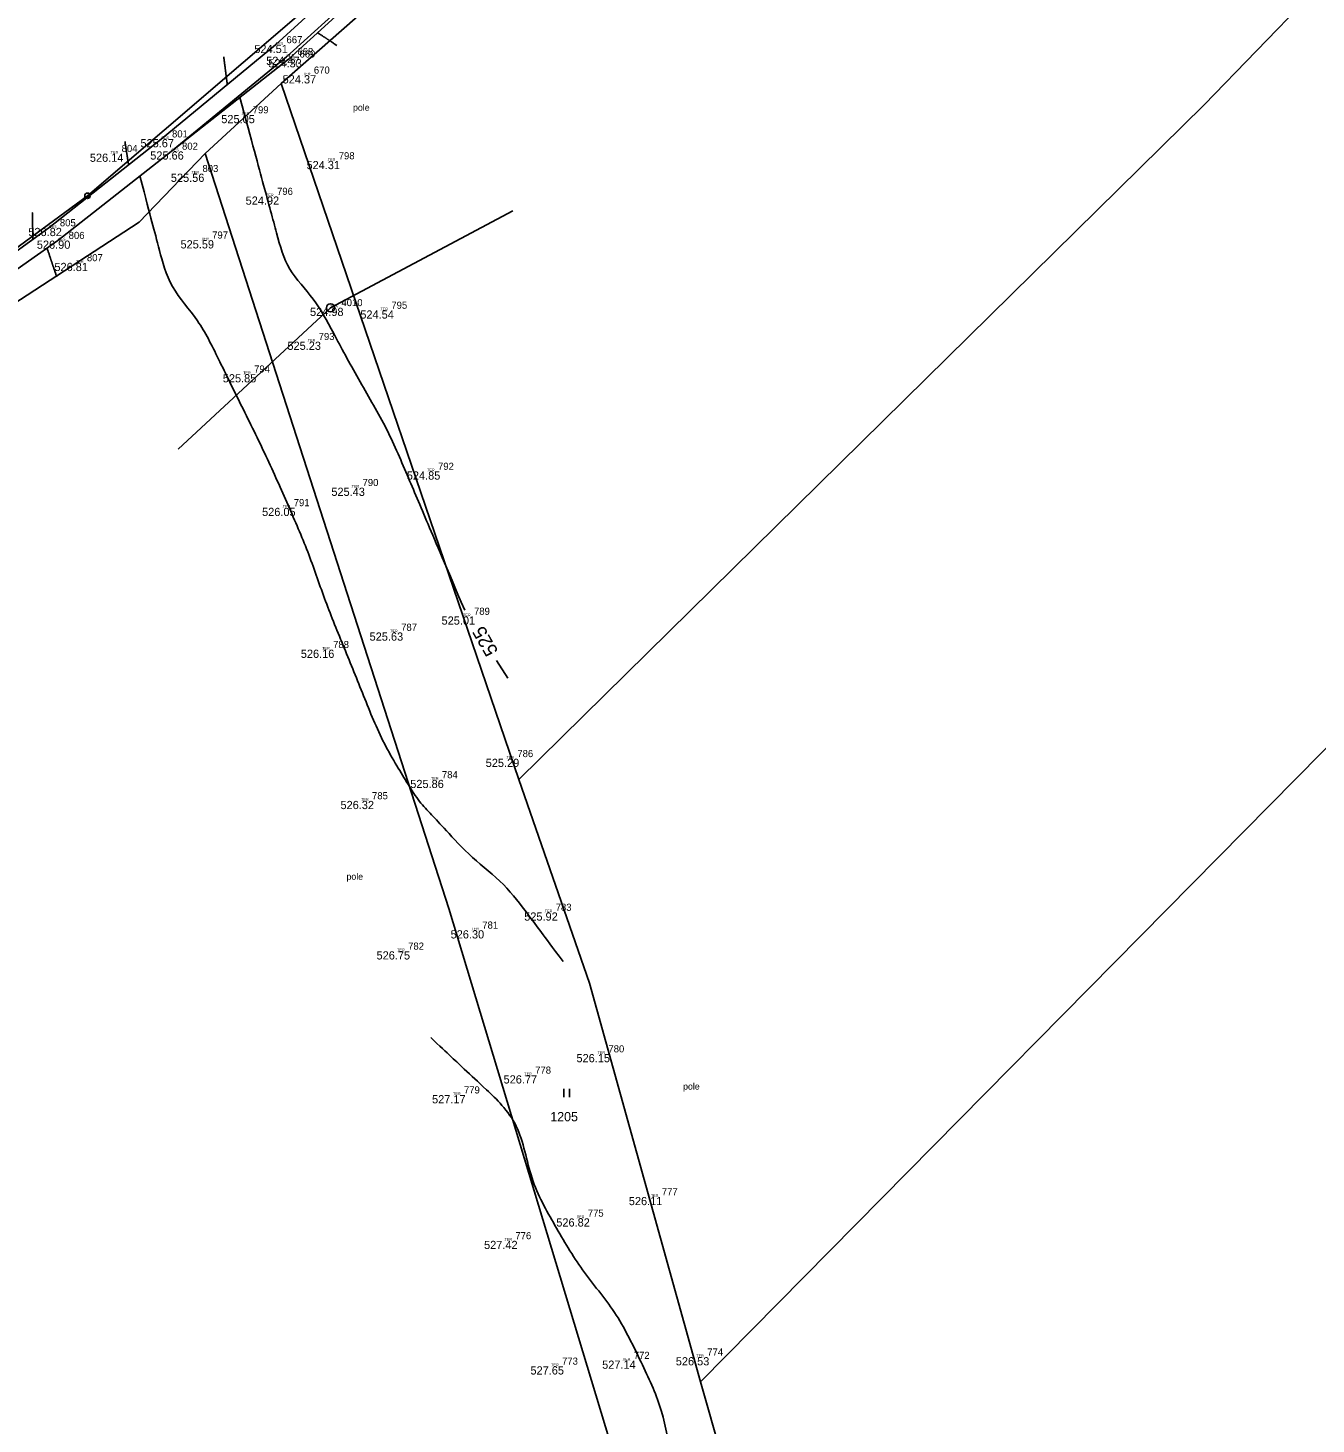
# Model space of a CAD drawing. Extents: x -604848 to -603227, y -1111879 to -1109838.
# Drawn here: x -604243.7 to -604007.9, y -1111222.3 to -1110966.8 of the extents above; entities that cross this region are included whole.
import ezdxf

# ---------------------------------------------------------------- set-up
doc = ezdxf.new("R2010")
doc.units = 0
for name, color, linetype in [('1', 7, 'Continuous'), ('10', 7, 'Continuous'), ('14', 7, 'Continuous'), ('18', 7, 'Continuous'), ('19', 7, 'Continuous'), ('20', 7, 'Continuous'), ('23', 7, 'Continuous'), ('28', 7, 'Continuous'), ('4', 7, 'Continuous'), ('5', 7, 'Continuous'), ('7', 7, 'Continuous'), ('9', 7, 'Continuous'), ('Default', 7, 'Continuous')]:
    doc.layers.add(name, color=color, linetype=linetype)

# ---------------------------------------------------------------- blocks, each defined once
blk = doc.blocks.new('Z105')
at = {"layer": '28'}
for radius in [0.5, 0.01]:
    blk.add_circle((0, 0), radius, dxfattribs=at)
blk = doc.blocks.new('Z3060')
at = {"layer": '23'}
for p, q in [((-0.5, 0), (-0.5, 1.5)), ((0.5, 1.5), (0.5, 0))]:
    blk.add_line(p, q, dxfattribs=at)
blk = doc.blocks.new('POINT_DISPLAY')
at = {"layer": 'Default'}
blk.add_line((0, 0), (0, 0), dxfattribs=at)
blk = doc.blocks.new('Z101')
at = {"layer": '28'}
for radius in [0.75, 0.01]:
    blk.add_circle((0, 0), radius, dxfattribs=at)

msp = doc.modelspace()

# ---------------------------------------------------------------- linework, layer by layer
at = {"layer": '1'}
for p, q in [((-603901.82, -1110850.22), (-604028.42, -1110980.89)), ((-604163.92, -1110938.59), (-604232.79, -1110997.55)), ((-604197.35, -1110977.02), (-604159.32, -1110943.54)), ((-604211.23, -1110989.83), (-604197.35, -1110977.02)), ((-604197.35, -1110977.02), (-604153.81, -1111104.35)), ((-604028.42, -1110980.89), (-604153.81, -1111104.35)), ((-604223.34, -1111002.38), (-604211.23, -1110989.83)), ((-604211.23, -1110989.83), (-604166.66, -1111127.93)), ((-604232.79, -1110997.55), (-604252.82, -1111012.29)), ((-604247.83, -1111018.35), (-604223.34, -1111002.38)), ((-604120.55, -1111214.55), (-603998.99, -1111091.42)), ((-604153.81, -1111104.35), (-604140.92, -1111141.64)), ((-604166.66, -1111127.93), (-604118.37, -1111287.69)), ((-604140.92, -1111141.64), (-604120.55, -1111214.55)), ((-604099.95, -1111287.39), (-604120.55, -1111214.55))]:
    msp.add_line(p, q, dxfattribs=at)
at = {"layer": '10'}
for p, q in [((-604175.57, -1110953.98), (-604195.98, -1110972.55)), ((-604195.98, -1110972.55), (-604217.47, -1110989.42))]:
    msp.add_line(p, q, dxfattribs=at)
at = {"layer": '4'}
for p, q in [((-604198.35, -1110969.93), (-604177.8, -1110951.09)), ((-604175.73, -1110953.43), (-604196.36, -1110972.1)), ((-604219.3, -1110987.17), (-604198.35, -1110969.93)), ((-604196.36, -1110972.1), (-604217.47, -1110989.42)), ((-604239.83, -1111003.42), (-604219.3, -1110987.17)), ((-604217.47, -1110989.42), (-604238.22, -1111005.74)), ((-604256.17, -1111015.13), (-604239.83, -1111003.42)), ((-604238.22, -1111005.74), (-604254.7, -1111017.36))]:
    msp.add_line(p, q, dxfattribs=at)
at = {"layer": '5'}
for q in [(-604154.93, -1111000.32), (-604216.18, -1111043.9)]:
    msp.add_line((-604188.3, -1111018.04), q, dxfattribs=at)
at = {"layer": '7'}
msp.add_line((-604155.85, -1111085.81), (-604157.9, -1111082.56), dxfattribs=at)
for points, degree in [([(-604190.65, -1110967.7), (-604189.48, -1110968.48), (-604188.31, -1110969.26), (-604187.14, -1110970.03)], 2), ([(-604207.19, -1110977.2), (-604207.4, -1110975.52), (-604207.62, -1110973.83), (-604207.83, -1110972.14)], 2), ([(-604163.74, -1111073.39), (-604167.23, -1111065.18), (-604170.72, -1111056.97), (-604174.21, -1111048.76), (-604178.1, -1111039.61), (-604183.29, -1111031.07), (-604187.95, -1111022.3), (-604191.14, -1111016.31), (-604196.31, -1111011.18), (-604198.09, -1111004.63), (-604200.36, -1110996.27), (-604202.62, -1110987.91), (-604204.89, -1110979.55)], 3), ([(-604225.26, -1110991.88), (-604225.48, -1110990.46), (-604225.7, -1110989.03), (-604225.92, -1110987.61)], 2), ([(-604145.73, -1111137.66), (-604147.79, -1111134.9), (-604149.85, -1111132.13), (-604151.91, -1111129.37), (-604156.39, -1111123.36), (-604162.47, -1111118.76), (-604167.54, -1111113.23), (-604169.78, -1111110.79), (-604172.11, -1111108.44), (-604173.87, -1111105.59), (-604178.96, -1111097.37), (-604182.43, -1111088.5), (-604186.05, -1111079.65), (-604189.49, -1111071.25), (-604192.34, -1111062.63), (-604195.99, -1111054.33), (-604200.04, -1111045.12), (-604204.54, -1111036.1), (-604208.96, -1111027.07), (-604212.29, -1111020.28), (-604217.78, -1111014.4), (-604219.71, -1111007.08), (-604220.88, -1111002.69), (-604222.03, -1110998.31), (-604223.19, -1110993.92)], 3), ([(-604242.76, -1111005.52), (-604242.8, -1111003.88), (-604242.83, -1111002.23), (-604242.87, -1111000.59)], 2), ([(-604240.18, -1111007.12), (-604239.59, -1111008.87), (-604239, -1111010.62), (-604238.41, -1111012.36)], 2), ([(-604107.47, -1111355.96), (-604108.69, -1111355.09), (-604109.9, -1111354.22), (-604111.11, -1111353.34), (-604112.81, -1111352.11), (-604113.35, -1111349.73), (-604114, -1111347.73), (-604114.9, -1111344.93), (-604115.79, -1111342.15), (-604116.6, -1111339.33), (-604117.69, -1111335.55), (-604118.69, -1111331.74), (-604119.76, -1111327.96), (-604120.92, -1111323.84), (-604123.63, -1111320.08), (-604124.13, -1111315.85), (-604124.69, -1111311.14), (-604122.89, -1111306.36), (-604122.71, -1111301.58), (-604122.5, -1111296.04), (-604122.18, -1111290.5), (-604122.23, -1111284.96), (-604122.29, -1111277.59), (-604122.63, -1111270.22), (-604122.97, -1111262.85), (-604123.38, -1111254.08), (-604124.18, -1111245.34), (-604125.08, -1111236.59), (-604126, -1111227.67), (-604127.68, -1111218.79), (-604131.66, -1111210.53), (-604135.98, -1111201.59), (-604142.42, -1111194.28), (-604147.23, -1111185.91), (-604151.95, -1111177.72), (-604153.4, -1111167.07), (-604160.35, -1111160.57), (-604163.55, -1111157.58), (-604166.75, -1111154.58), (-604169.95, -1111151.59)], 3)]:
    msp.add_open_spline(points, degree=degree, dxfattribs=at)

# ---------------------------------------------------------------- block references
at = {"layer": '18'}
for p in [(-604198.35, -1110969.93), (-604196.36, -1110972.1), (-604195.98, -1110972.55), (-604193.34, -1110975.49), (-604204.53, -1110982.76), (-604219.3, -1110987.17), (-604228.52, -1110989.83), (-604217.47, -1110989.42), (-604188.79, -1110991.17), (-604213.73, -1110993.5), (-604200.08, -1110997.68), (-604239.83, -1111003.42), (-604238.22, -1111005.74), (-604211.96, -1111005.68), (-604234.88, -1111009.82), (-604188.3, -1111018.04), (-604179.16, -1111018.52), (-604192.46, -1111024.24), (-604204.28, -1111030.19), (-604170.62, -1111047.99), (-604184.43, -1111050.96), (-604197.03, -1111054.64), (-604164.03, -1111074.52), (-604177.37, -1111077.45), (-604189.82, -1111080.6), (-604156.1, -1111100.56), (-604169.91, -1111104.42), (-604182.7, -1111108.27), (-604149.08, -1111128.68), (-604162.52, -1111131.94), (-604176.09, -1111135.79), (-604139.43, -1111154.59), (-604152.84, -1111158.48), (-604165.87, -1111162.11), (-604129.66, -1111180.74), (-604143.21, -1111184.66), (-604156.46, -1111188.77), (-604147.92, -1111211.73), (-604134.79, -1111210.68), (-604121.34, -1111210.06)]:
    msp.add_blockref('POINT_DISPLAY', p, dxfattribs=at)
at = {"layer": '23'}
msp.add_blockref('Z3060', (-604145.07, -1111162.46), dxfattribs=at)
at = {"layer": '28'}
msp.add_blockref('Z105', (-604232.79, -1110997.55), dxfattribs=at)
at = {"layer": '5'}
msp.add_blockref('Z101', (-604188.3, -1111018.04), dxfattribs=at)

# ---------------------------------------------------------------- texts
at = {"layer": '14'}
msp.add_text('1205', height=1.7, dxfattribs=at).set_placement((-604148.07, -1111166.9))
at = {"layer": '18'}
for s, p in [('CES', (-604198.35, -1110969.93)), ('CES', (-604196.36, -1110972.1)), ('POL', (-604195.98, -1110972.55)), ('TER', (-604193.34, -1110975.49)), ('TER', (-604204.53, -1110982.76)), ('CES', (-604219.3, -1110987.17)), ('TER', (-604228.52, -1110989.83)), ('CES', (-604217.47, -1110989.42)), ('TER', (-604188.79, -1110991.17)), ('TER', (-604213.73, -1110993.5)), ('TER', (-604200.08, -1110997.68)), ('CES', (-604239.83, -1111003.42)), ('CES', (-604238.22, -1111005.74)), ('TER', (-604211.96, -1111005.68)), ('TER', (-604234.88, -1111009.82)), ('STA', (-604188.3, -1111018.04)), ('TER', (-604179.16, -1111018.52)), ('TER', (-604192.46, -1111024.24)), ('TER', (-604204.28, -1111030.19)), ('TER', (-604170.62, -1111047.99)), ('TER', (-604184.43, -1111050.96)), ('TER', (-604197.03, -1111054.64)), ('TER', (-604164.03, -1111074.52)), ('TER', (-604177.37, -1111077.45)), ('TER', (-604189.82, -1111080.6)), ('TER', (-604156.1, -1111100.56)), ('TER', (-604169.91, -1111104.42)), ('TER', (-604182.7, -1111108.27)), ('TER', (-604149.08, -1111128.68)), ('TER', (-604162.52, -1111131.94)), ('TER', (-604176.09, -1111135.79)), ('TER', (-604139.43, -1111154.59)), ('TER', (-604152.84, -1111158.48)), ('TER', (-604165.87, -1111162.11)), ('TER', (-604129.66, -1111180.74)), ('TER', (-604143.21, -1111184.66)), ('TER', (-604156.46, -1111188.77)), ('TER', (-604121.34, -1111210.06)), ('TER', (-604147.92, -1111211.73)), ('TER', (-604134.79, -1111210.68))]:
    msp.add_text(s, height=0.5, dxfattribs=at).set_placement(p)
at = {"layer": '19'}
for s, p in [('667', (-604196.35, -1110969.63)), ('668', (-604194.36, -1110971.8)), ('669', (-604193.98, -1110972.25)), ('670', (-604191.34, -1110975.19)), ('799', (-604202.53, -1110982.46)), ('801', (-604217.3, -1110986.87)), ('804', (-604226.52, -1110989.53)), ('802', (-604215.47, -1110989.12)), ('798', (-604186.79, -1110990.87)), ('803', (-604211.73, -1110993.2)), ('796', (-604198.08, -1110997.38)), ('805', (-604237.83, -1111003.12)), ('806', (-604236.22, -1111005.44)), ('797', (-604209.96, -1111005.38)), ('807', (-604232.88, -1111009.52)), ('4010', (-604186.3, -1111017.74)), ('795', (-604177.16, -1111018.22)), ('793', (-604190.46, -1111023.94)), ('794', (-604202.28, -1111029.89)), ('792', (-604168.62, -1111047.69)), ('790', (-604182.43, -1111050.66)), ('791', (-604195.03, -1111054.34)), ('789', (-604162.03, -1111074.22)), ('787', (-604175.37, -1111077.15)), ('788', (-604187.82, -1111080.3)), ('786', (-604154.1, -1111100.26)), ('784', (-604167.91, -1111104.12)), ('785', (-604180.7, -1111107.97)), ('783', (-604147.08, -1111128.38)), ('781', (-604160.52, -1111131.64)), ('782', (-604174.09, -1111135.49)), ('780', (-604137.43, -1111154.29)), ('778', (-604150.84, -1111158.18)), ('779', (-604163.87, -1111161.81)), ('777', (-604127.66, -1111180.44)), ('775', (-604141.21, -1111184.36)), ('776', (-604154.46, -1111188.47)), ('772', (-604132.79, -1111210.38)), ('774', (-604119.34, -1111209.76)), ('773', (-604145.92, -1111211.43))]:
    msp.add_text(s, height=1.3, dxfattribs=at).set_placement(p)
at = {"layer": '20'}
for s, p in [('524.51 ', (-604202.24, -1110971.43)), ('524.47 ', (-604200.07, -1110973.6)), ('524.33 ', (-604199.69, -1110974.05)), ('524.37 ', (-604197.06, -1110976.99)), ('525.05 ', (-604208.29, -1110984.26)), ('525.67 ', (-604223.08, -1110988.67)), ('526.14 ', (-604232.34, -1110991.33)), ('525.66 ', (-604221.29, -1110990.92)), ('524.31 ', (-604192.69, -1110992.67)), ('525.56 ', (-604217.52, -1110995)), ('524.92 ', (-604203.83, -1110999.18)), ('526.82 ', (-604243.6, -1111004.92)), ('526.90 ', (-604242.05, -1111007.24)), ('525.59 ', (-604215.75, -1111007.18)), ('526.81 ', (-604238.83, -1111011.32)), ('524.98 ', (-604192.05, -1111019.54)), ('524.54 ', (-604182.84, -1111020.02)), ('525.23 ', (-604196.18, -1111025.74)), ('525.85 ', (-604208.01, -1111031.69)), ('524.85 ', (-604174.33, -1111049.49)), ('525.43 ', (-604188.14, -1111052.46)), ('526.05 ', (-604200.82, -1111056.14)), ('525.01 ', (-604167.97, -1111076.02)), ('525.63 ', (-604181.14, -1111078.95)), ('526.16 ', (-604193.73, -1111082.1)), ('525.29 ', (-604159.89, -1111102.06)), ('525.86 ', (-604173.7, -1111105.92)), ('526.32 ', (-604186.47, -1111109.77)), ('525.92 ', (-604152.84, -1111130.18)), ('526.30 ', (-604166.31, -1111133.44)), ('526.75 ', (-604179.87, -1111137.29)), ('526.15 ', (-604143.28, -1111156.09)), ('526.77 ', (-604156.62, -1111159.98)), ('527.17 ', (-604169.71, -1111163.61)), ('526.11 ', (-604133.7, -1111182.24)), ('526.82 ', (-604146.97, -1111186.16)), ('527.42 ', (-604160.19, -1111190.27)), ('527.65 ', (-604151.7, -1111213.23)), ('527.14 ', (-604138.58, -1111212.18)), ('526.53 ', (-604125.1, -1111211.56))]:
    msp.add_text(s, height=1.5, dxfattribs=at).set_placement(p)
at = {"layer": '7'}
msp.add_text('525', height=2.5, rotation=119.7, dxfattribs=at).set_placement((-604157.54, -1111080.88))
at = {"layer": '9'}
for p in [(-604184.17, -1110981.99), (-604185.37, -1111122.71), (-604123.76, -1111161.1)]:
    msp.add_text('pole', height=1.2, dxfattribs=at).set_placement(p)

doc.saveas('drawing.dxf')
